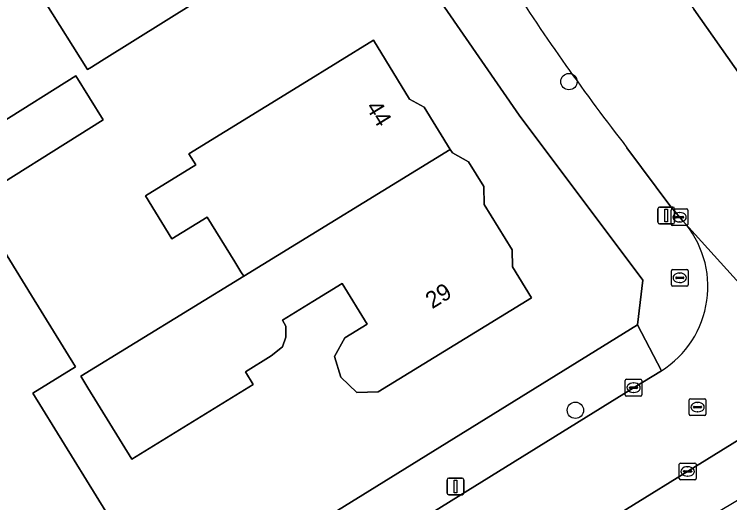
# Model space of a CAD drawing. Extents: x 161347 to 161881, y 382161 to 382804.
# Drawn here: x 161629.51 to 161672.27, y 382307.02 to 382336.2 of the extents above; entities that cross this region are included whole.
import ezdxf

# ---------------------------------------------------------------- set-up
doc = ezdxf.new("R2010")
doc.units = 0
for name, color, linetype in [('IMGEO_Boom', 7, 'Continuous'), ('IMGEO_Brandkraan', 7, 'Continuous'), ('IMGEO_Erf', 7, 'Continuous'), ('IMGEO_Kolk', 7, 'Continuous'), ('IMGEO_Lichtmast', 7, 'Continuous'), ('IMGEO_Pand', 7, 'Continuous'), ('IMGEO_Pand_nummerreeks', 7, 'Continuous'), ('IMGEO_Rijbaan_lokaal_gesloten', 7, 'Continuous'), ('IMGEO_Rijbaan_lokaal_open', 7, 'Continuous'), ('IMGEO_Rioolput', 7, 'Continuous'), ('IMGEO_Voetpad_open', 7, 'Continuous')]:
    doc.layers.add(name, color=color, linetype=linetype)

msp = doc.modelspace()

# ---------------------------------------------------------------- linework, layer by layer
at = {"layer": 'IMGEO_Boom'}
for centre in [(161662.662, 382332.181), (161663.048, 382312.541)]:
    msp.add_circle(centre, 0.489, dxfattribs=at)
at = {"layer": 'IMGEO_Brandkraan'}
for p, q in [((161668.783, 382320.03), (161668.783, 382320.882)), ((161668.858, 382320.956), (161669.71, 382320.956)), ((161669.271, 382320.736), (161669.296, 382320.736)), ((161669.784, 382320.882), (161669.784, 382320.03)), ((161669.042, 382320.45), (161669.042, 382320.462)), ((161669.48, 382320.413), (161669.082, 382320.413)), ((161669.085, 382320.499), (161669.483, 382320.499)), ((161669.526, 382320.462), (161669.526, 382320.45)), ((161669.71, 382319.956), (161668.858, 382319.956)), ((161669.294, 382320.176), (161669.269, 382320.176))]:
    msp.add_line(p, q, dxfattribs=at)
for points in [[(161668.783, 382320.03), (161668.783, 382320.882)], [(161668.858, 382320.956), (161669.71, 382320.956)], [(161669.784, 382320.882), (161669.784, 382320.03)], [(161669.71, 382319.956), (161668.858, 382319.956)]]:
    msp.add_lwpolyline(points, dxfattribs=at)
for centre, radius, start, end in [((161668.86, 382320.88), 0.0765, 91.552, 178.448), ((161668.86, 382320.88), 0.0765, 91.552, 178.448), ((161669.708, 382320.88), 0.0765, 1.552, 88.448), ((161669.708, 382320.88), 0.0765, 1.552, 88.448), ((161669.082, 382320.459), 0.0403, 85.8775, 175.7526), ((161669.079, 382320.449), 0.0366, 178.938, 274.7102), ((161669.483, 382320.456), 0.043, 264.8664, 352.4533), ((161669.487, 382320.461), 0.0386, 1.7309, 96.639), ((161668.86, 382320.032), 0.0765, 181.552, 268.448), ((161668.86, 382320.032), 0.0765, 181.552, 268.448), ((161669.708, 382320.032), 0.0765, 271.552, 358.448), ((161669.708, 382320.032), 0.0765, 271.552, 358.448)]:
    msp.add_arc(centre, radius, start, end, dxfattribs=at)
for centre, major_axis, ratio, start_param, end_param in [((161669.27, 382320.456), (-0.387, 0.002), 0.722429, 4.712389, 7.853982), ((161669.295, 382320.456), (-0.39, 0.002), 0.717154, 1.570796, 4.712389)]:
    msp.add_ellipse(centre, major_axis=major_axis, ratio=ratio, start_param=start_param, end_param=end_param, dxfattribs=at)
at = {"layer": 'IMGEO_Erf'}
for points in [[(161666.754, 382317.654), (161667.07, 382320.321), (161659.692, 382330.179), (161655.232, 382336.622), (161650.949, 382343.545), (161642.516, 382357.177), (161640.84, 382359.886), (161634.67, 382369.86), (161632.808, 382372.87), (161625.285, 382385.031)], [(161646.005, 382340.464), (161634.717, 382333.413), (161634.132, 382333.047), (161633.892, 382332.897), (161631.356, 382336.918)], [(161627.927, 382323.616), (161630.537, 382319.392), (161633.165, 382315.138), (161630.612, 382313.56), (161636.293, 382304.363), (161632.349, 382301.927), (161632.107, 382300.902), (161631.199, 382300.341), (161630.161, 382300.586), (161629.4, 382300.115)], [(161612.505, 382284.052), (161619.461, 382288.113), (161619.333, 382288.314), (161666.754, 382317.654)]]:
    msp.add_lwpolyline(points, dxfattribs=at)
for points in [[(161650.971, 382334.65), (161653.141, 382331.12), (161654.017, 382330.647), (161655.565, 382328.129), (161655.695, 382327.918), (161656.665, 382327.393), (161657.571, 382325.92), (161657.601, 382324.835), (161659.268, 382322.123), (161659.296, 382321.107), (161660.428, 382319.267), (161651.266, 382313.634), (161649.99, 382313.599), (161649.034, 382314.521), (161648.658, 382315.748), (161649.268, 382316.875), (161650.595, 382317.691), (161649.106, 382320.113), (161647.363, 382319.042), (161645.535, 382317.918), (161645.749, 382317.569), (161645.741, 382316.916), (161645.543, 382316.331), (161644.874, 382315.786), (161643.332, 382314.838), (161643.791, 382314.091), (161636.53, 382309.627), (161633.911, 382313.887), (161633.489, 382314.574), (161643.221, 382320.55), (161643.059, 382320.813), (161642.694, 382321.407), (161641.045, 382324.087), (161638.93, 382322.787), (161637.348, 382325.36), (161640.353, 382327.208), (161639.945, 382327.87), (161646.712, 382332.031)], [(161624.069, 382328.546), (161627.833, 382330.897), (161628.603, 382329.665), (161633.186, 382332.528), (161634.831, 382329.9), (161626.488, 382324.676)]]:
    msp.add_lwpolyline(points, close=True, dxfattribs=at)
at = {"layer": 'IMGEO_Kolk'}
for p, q in [((161668.849, 382324.574), (161669.701, 382324.574)), ((161668.774, 382323.648), (161668.774, 382324.5)), ((161669.262, 382324.354), (161669.287, 382324.354)), ((161669.775, 382324.5), (161669.775, 382323.648)), ((161669.033, 382324.068), (161669.033, 382324.08)), ((161669.471, 382324.031), (161669.073, 382324.031)), ((161669.076, 382324.117), (161669.474, 382324.117)), ((161669.285, 382323.794), (161669.26, 382323.794)), ((161669.517, 382324.08), (161669.517, 382324.068)), ((161669.701, 382323.574), (161668.849, 382323.574)), ((161666.024, 382313.466), (161666.024, 382314.318)), ((161666.099, 382314.392), (161666.951, 382314.392)), ((161667.025, 382314.318), (161667.025, 382313.466)), ((161666.283, 382313.886), (161666.283, 382313.898)), ((161666.326, 382313.935), (161666.724, 382313.935)), ((161666.512, 382314.172), (161666.537, 382314.172)), ((161666.767, 382313.898), (161666.767, 382313.886)), ((161666.721, 382313.849), (161666.323, 382313.849)), ((161666.535, 382313.612), (161666.51, 382313.612)), ((161666.951, 382313.392), (161666.099, 382313.392)), ((161669.256, 382308.464), (161669.256, 382309.316)), ((161669.331, 382309.39), (161670.183, 382309.39)), ((161670.257, 382309.316), (161670.257, 382308.464)), ((161669.515, 382308.884), (161669.515, 382308.896)), ((161669.953, 382308.847), (161669.555, 382308.847)), ((161669.558, 382308.933), (161669.956, 382308.933)), ((161669.744, 382309.17), (161669.769, 382309.17)), ((161669.999, 382308.896), (161669.999, 382308.884)), ((161670.183, 382308.39), (161669.331, 382308.39)), ((161669.767, 382308.61), (161669.742, 382308.61))]:
    msp.add_line(p, q, dxfattribs=at)
for points in [[(161668.849, 382324.574), (161669.701, 382324.574)], [(161668.774, 382323.648), (161668.774, 382324.5)], [(161669.775, 382324.5), (161669.775, 382323.648)], [(161669.701, 382323.574), (161668.849, 382323.574)], [(161666.024, 382313.466), (161666.024, 382314.318)], [(161666.099, 382314.392), (161666.951, 382314.392)], [(161667.025, 382314.318), (161667.025, 382313.466)], [(161666.951, 382313.392), (161666.099, 382313.392)], [(161669.256, 382308.464), (161669.256, 382309.316)], [(161669.331, 382309.39), (161670.183, 382309.39)], [(161670.257, 382309.316), (161670.257, 382308.464)], [(161670.183, 382308.39), (161669.331, 382308.39)]]:
    msp.add_lwpolyline(points, dxfattribs=at)
for centre, radius, start, end in [((161668.851, 382324.498), 0.0765, 91.552, 178.448), ((161668.851, 382324.498), 0.0765, 91.552, 178.448), ((161669.699, 382324.498), 0.0765, 1.552, 88.448), ((161669.699, 382324.498), 0.0765, 1.552, 88.448), ((161669.073, 382324.077), 0.0403, 85.8775, 175.7526), ((161669.07, 382324.067), 0.0366, 178.938, 274.7102), ((161669.474, 382324.074), 0.043, 264.8664, 352.4533), ((161669.478, 382324.079), 0.0386, 1.7309, 96.639), ((161668.851, 382323.65), 0.0765, 181.552, 268.448), ((161668.851, 382323.65), 0.0765, 181.552, 268.448), ((161669.699, 382323.65), 0.0765, 271.552, 358.448), ((161669.699, 382323.65), 0.0765, 271.552, 358.448), ((161666.101, 382314.316), 0.0765, 91.552, 178.448), ((161666.101, 382314.316), 0.0765, 91.552, 178.448), ((161666.949, 382314.316), 0.0765, 1.552, 88.448), ((161666.949, 382314.316), 0.0765, 1.552, 88.448), ((161666.323, 382313.895), 0.0403, 85.8775, 175.7526), ((161666.32, 382313.885), 0.0366, 178.938, 274.7102), ((161666.724, 382313.892), 0.043, 264.8664, 352.4533), ((161666.728, 382313.897), 0.0386, 1.7309, 96.639), ((161666.101, 382313.468), 0.0765, 181.552, 268.448), ((161666.101, 382313.468), 0.0765, 181.552, 268.448), ((161666.949, 382313.468), 0.0765, 271.552, 358.448), ((161666.949, 382313.468), 0.0765, 271.552, 358.448), ((161669.333, 382309.314), 0.0765, 91.552, 178.448), ((161669.333, 382309.314), 0.0765, 91.552, 178.448), ((161670.181, 382309.314), 0.0765, 1.552, 88.448), ((161670.181, 382309.314), 0.0765, 1.552, 88.448), ((161669.555, 382308.893), 0.0403, 85.8775, 175.7526), ((161669.552, 382308.883), 0.0366, 178.938, 274.7102), ((161669.956, 382308.89), 0.043, 264.8664, 352.4533), ((161669.96, 382308.895), 0.0386, 1.7309, 96.639), ((161669.333, 382308.466), 0.0765, 181.552, 268.448), ((161669.333, 382308.466), 0.0765, 181.552, 268.448), ((161670.181, 382308.466), 0.0765, 271.552, 358.448), ((161670.181, 382308.466), 0.0765, 271.552, 358.448)]:
    msp.add_arc(centre, radius, start, end, dxfattribs=at)
for centre, major_axis, ratio, start_param, end_param in [((161669.261, 382324.074), (-0.387, 0.002), 0.722429, 4.712389, 7.853982), ((161669.286, 382324.074), (-0.39, 0.002), 0.717154, 1.570796, 4.712389), ((161666.511, 382313.892), (-0.387, 0.002), 0.722429, 4.712389, 7.853982), ((161666.536, 382313.892), (-0.39, 0.002), 0.717154, 1.570796, 4.712389), ((161669.743, 382308.89), (-0.387, 0.002), 0.722429, 4.712389, 7.853982), ((161669.768, 382308.89), (-0.39, 0.002), 0.717154, 1.570796, 4.712389)]:
    msp.add_ellipse(centre, major_axis=major_axis, ratio=ratio, start_param=start_param, end_param=end_param, dxfattribs=at)
at = {"layer": 'IMGEO_Lichtmast'}
for p, q in [((161667.981, 382323.779), (161667.981, 382324.579)), ((161667.981, 382324.579), (161667.981, 382323.779)), ((161668.081, 382324.679), (161668.871, 382324.679)), ((161668.871, 382324.679), (161668.081, 382324.679)), ((161668.971, 382324.579), (161668.971, 382323.779)), ((161668.971, 382323.779), (161668.971, 382324.579)), ((161668.871, 382323.679), (161668.081, 382323.679)), ((161668.081, 382323.679), (161668.871, 382323.679)), ((161655.381, 382307.592), (161655.381, 382308.392)), ((161655.381, 382308.392), (161655.381, 382307.592)), ((161655.481, 382308.492), (161656.271, 382308.492)), ((161656.271, 382308.492), (161655.481, 382308.492)), ((161656.371, 382308.392), (161656.371, 382307.592)), ((161656.371, 382307.592), (161656.371, 382308.392)), ((161656.271, 382307.492), (161655.481, 382307.492)), ((161655.481, 382307.492), (161656.271, 382307.492))]:
    msp.add_line(p, q, dxfattribs=at)
for points in [[(161668.401, 382324.554), (161668.551, 382324.554), (161668.551, 382323.804), (161668.401, 382323.804), (161668.401, 382324.554)], [(161655.801, 382308.367), (161655.951, 382308.367), (161655.951, 382307.617), (161655.801, 382307.617), (161655.801, 382308.367)]]:
    msp.add_lwpolyline(points, dxfattribs=at)
for centre, start, end in [((161668.081, 382324.579), 90, 180), ((161668.081, 382324.579), 90, 180), ((161668.871, 382324.579), 0, 90), ((161668.871, 382324.579), 360, 90), ((161668.081, 382323.779), 180, 270), ((161668.081, 382323.779), 180, 270), ((161668.871, 382323.779), 270, 0), ((161668.871, 382323.779), 270, 0), ((161655.481, 382308.392), 90, 180), ((161655.481, 382308.392), 90, 180), ((161656.271, 382308.392), 0, 90), ((161656.271, 382308.392), 360, 90), ((161655.481, 382307.592), 180, 270), ((161655.481, 382307.592), 180, 270), ((161656.271, 382307.592), 270, 0), ((161656.271, 382307.592), 270, 0)]:
    msp.add_arc(centre, 0.1, start, end, dxfattribs=at)
at = {"layer": 'IMGEO_Pand'}
for points in [[(161643.329, 382348.208), (161631.779, 382340.932), (161633.464, 382338.235), (161631.595, 382337.068), (161631.356, 382336.918), (161633.892, 382332.897), (161634.132, 382333.047), (161634.717, 382333.413), (161646.005, 382340.464), (161646.375, 382342.068), (161644.954, 382344.342), (161644.908, 382345.681)], [(161655.565, 382328.129), (161654.017, 382330.647), (161653.141, 382331.12), (161650.971, 382334.65), (161646.712, 382332.031), (161639.945, 382327.87), (161640.353, 382327.208), (161637.348, 382325.36), (161638.93, 382322.787), (161641.045, 382324.087), (161642.694, 382321.407), (161643.059, 382320.813), (161643.221, 382320.55)], [(161634.831, 382329.9), (161633.186, 382332.528), (161628.603, 382329.665), (161627.833, 382330.897), (161624.069, 382328.546), (161626.488, 382324.676)], [(161643.332, 382314.838), (161644.874, 382315.786), (161645.543, 382316.331), (161645.741, 382316.916), (161645.749, 382317.569), (161645.535, 382317.918), (161647.363, 382319.042), (161649.106, 382320.113), (161650.595, 382317.691), (161649.268, 382316.875), (161648.658, 382315.748), (161649.034, 382314.521), (161649.99, 382313.599), (161651.266, 382313.634), (161660.428, 382319.267), (161659.296, 382321.107), (161659.268, 382322.123), (161657.601, 382324.835), (161657.571, 382325.92), (161656.665, 382327.393), (161655.695, 382327.918), (161655.565, 382328.129), (161643.221, 382320.55), (161633.489, 382314.574), (161633.911, 382313.887), (161636.53, 382309.627), (161643.791, 382314.091)], [(161629.4, 382300.115), (161630.161, 382300.586), (161631.199, 382300.341), (161632.107, 382300.902), (161632.349, 382301.927), (161636.293, 382304.363), (161630.612, 382313.56), (161633.165, 382315.138), (161630.537, 382319.392), (161627.927, 382323.616), (161624.985, 382321.799), (161628.545, 382316.037), (161622.141, 382312.082), (161622.812, 382310.996), (161622.718, 382310.938)]]:
    msp.add_lwpolyline(points, close=True, dxfattribs=at)
at = {"layer": 'IMGEO_Rijbaan_lokaal_gesloten'}
for points in [[(161672.905, 382332.54), (161670.126, 382336.516)], [(161666.128, 382328.229), (161668.748, 382324.693), (161669.454, 382323.886), (161675.695, 382316.977), (161680.957, 382311.996), (161682.033, 382311.039), (161683.751, 382309.654), (161686.143, 382307.952)]]:
    msp.add_lwpolyline(points, dxfattribs=at)
msp.add_arc((161775.821, 382413.444), 138.903, 212.78666, 217.84181, dxfattribs=at)
at = {"layer": 'IMGEO_Rijbaan_lokaal_open'}
for points in [[(161680.957, 382311.996), (161675.695, 382316.977), (161669.454, 382323.886)], [(161668.184, 382314.902), (161666.523, 382313.889), (161650.804, 382304.153), (161650.157, 382303.754), (161639.777, 382297.347), (161634.126, 382293.868), (161632.48, 382292.857), (161635.555, 382287.777), (161637.303, 382288.856), (161641.382, 382291.368), (161645.583, 382293.956), (161653.759, 382298.992), (161661.309, 382303.664), (161675.035, 382312.158)]]:
    msp.add_lwpolyline(points, dxfattribs=at)
msp.add_arc((161665.028, 382319.93), 5.936, 302.1144, 41.7933, dxfattribs=at)
at = {"layer": 'IMGEO_Rioolput'}
for p, q in [((161669.847, 382312.306), (161669.847, 382313.158)), ((161669.922, 382313.232), (161670.774, 382313.232)), ((161670.848, 382313.158), (161670.848, 382312.306)), ((161670.106, 382312.726), (161670.106, 382312.738)), ((161670.544, 382312.689), (161670.146, 382312.689)), ((161670.149, 382312.775), (161670.547, 382312.775)), ((161670.335, 382313.012), (161670.36, 382313.012)), ((161670.59, 382312.738), (161670.59, 382312.726)), ((161670.774, 382312.232), (161669.922, 382312.232)), ((161670.358, 382312.452), (161670.333, 382312.452))]:
    msp.add_line(p, q, dxfattribs=at)
for points in [[(161669.847, 382312.306), (161669.847, 382313.158)], [(161669.922, 382313.232), (161670.774, 382313.232)], [(161670.848, 382313.158), (161670.848, 382312.306)], [(161670.774, 382312.232), (161669.922, 382312.232)]]:
    msp.add_lwpolyline(points, dxfattribs=at)
for centre, radius, start, end in [((161669.924, 382313.156), 0.0765, 91.552, 178.448), ((161669.924, 382313.156), 0.0765, 91.552, 178.448), ((161670.772, 382313.156), 0.0765, 1.552, 88.448), ((161670.772, 382313.156), 0.0765, 1.552, 88.448), ((161670.146, 382312.735), 0.0403, 85.8775, 175.7526), ((161670.143, 382312.725), 0.0366, 178.938, 274.7102), ((161670.547, 382312.732), 0.043, 264.8664, 352.4533), ((161670.551, 382312.737), 0.0386, 1.7309, 96.639), ((161669.924, 382312.308), 0.0765, 181.552, 268.448), ((161669.924, 382312.308), 0.0765, 181.552, 268.448), ((161670.772, 382312.308), 0.0765, 271.552, 358.448), ((161670.772, 382312.308), 0.0765, 271.552, 358.448)]:
    msp.add_arc(centre, radius, start, end, dxfattribs=at)
for centre, major_axis, ratio, start_param, end_param in [((161670.334, 382312.732), (-0.387, 0.002), 0.722429, 4.712389, 7.853982), ((161670.359, 382312.732), (-0.39, 0.002), 0.717154, 1.570796, 4.712389)]:
    msp.add_ellipse(centre, major_axis=major_axis, ratio=ratio, start_param=start_param, end_param=end_param, dxfattribs=at)
at = {"layer": 'IMGEO_Voetpad_open'}
msp.add_lwpolyline([(161670.894, 382342.449), (161666.872, 382341.08), (161670.126, 382336.516), (161672.905, 382332.54), (161675.39, 382336.184), (161673.167, 382339.282)], close=True, dxfattribs=at)
for points in [[(161659.046, 382338.226), (161655.232, 382336.622), (161659.692, 382330.179), (161667.07, 382320.321), (161666.754, 382317.654), (161668.184, 382314.902)], [(161669.454, 382323.886), (161668.748, 382324.693), (161666.128, 382328.229)], [(161620.698, 382285.57), (161627.466, 382289.739), (161630.045, 382291.331), (161632.48, 382292.857), (161634.126, 382293.868), (161639.777, 382297.347), (161639.517, 382297.769), (161649.9, 382304.17), (161650.157, 382303.754), (161650.804, 382304.153), (161666.523, 382313.889), (161668.184, 382314.902), (161666.754, 382317.654), (161619.333, 382288.314), (161619.461, 382288.113), (161612.505, 382284.052)], [(161671.693, 382306.549), (161677.151, 382309.804), (161675.035, 382312.158), (161661.309, 382303.664), (161653.759, 382298.992), (161645.583, 382293.956), (161641.382, 382291.368), (161637.303, 382288.856), (161635.555, 382287.777), (161633.128, 382286.258), (161628.72, 382283.536), (161628.112, 382283.168), (161620.383, 382278.485), (161618.896, 382277.584)]]:
    msp.add_lwpolyline(points, dxfattribs=at)
for centre, radius, start, end in [((161775.821, 382413.444), 138.903, 212.78666, 217.84181), ((161665.028, 382319.93), 5.936, 302.1144, 41.7933)]:
    msp.add_arc(centre, radius, start, end, dxfattribs=at)

# ---------------------------------------------------------------- texts
at = {"layer": 'IMGEO_Pand_nummerreeks'}
for s, rotation, p in [('44', 301.5812, (161650.491, 382330.657)), ('29', 31.5814, (161654.485, 382318.572))]:
    msp.add_text(s, height=1, rotation=rotation, dxfattribs=at).set_placement(p)

doc.saveas('drawing.dxf')
